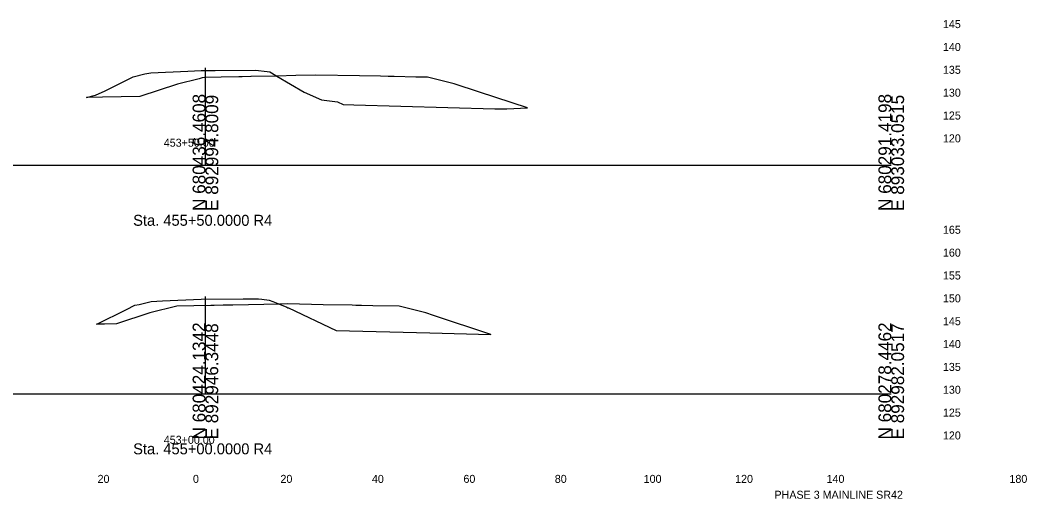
# Model space of a CAD drawing. Extents: x 21059 to 22955, y 6470 to 17494.
# Drawn here: x 21604.3 to 21824.5, y 7391.8 to 7496.6 of the extents above; entities that cross this region are included whole.
import ezdxf

# ---------------------------------------------------------------- set-up
doc = ezdxf.new("R2010")
doc.units = 0
for name, color, linetype in [('CONST_DCH', 7, 'Continuous'), ('Draft_XS_Grid', 7, 'Continuous'), ('Draft_XS_Text', 7, 'Continuous'), ('DTM CONTOURS_MAJOR', 7, 'Continuous'), ('SLOPE_STAKES_FILL', 7, 'Continuous'), ('X_PROFILES_1', 7, 'Continuous'), ('XS_SHEET_EW_TX_VOLUME', 7, 'Continuous')]:
    doc.layers.add(name, color=color, linetype=linetype)

msp = doc.modelspace()

# ---------------------------------------------------------------- linework, layer by layer
at = {"layer": 'DTM CONTOURS_MAJOR'}
for p, q in [((21644.84, 7464.84), (21644.84, 7486.16)), ((21494.84, 7464.84), (21644.84, 7464.84)), ((21644.84, 7464.84), (21794.84, 7464.84)), ((21644.84, 7414.84), (21644.84, 7436.1)), ((21494.84, 7414.84), (21644.84, 7414.84)), ((21644.84, 7414.84), (21794.84, 7414.84))]:
    msp.add_line(p, q, dxfattribs=at)
at = {"layer": 'XS_SHEET_EW_TX_VOLUME'}
for points in [[(21618.8, 7479.63), (21620.79, 7480.15), (21622.92, 7481.11), (21629.06, 7484.21), (21631.58, 7484.82), (21632.92, 7485.05), (21641.01, 7485.41), (21643.9, 7485.53), (21646.97, 7485.55), (21655.77, 7485.64), (21658.33, 7485.33), (21658.82, 7485.26), (21658.91, 7485.24), (21659.27, 7485.09), (21660.49, 7484.36), (21654.87, 7484.25), (21654.77, 7484.25), (21652.85, 7484.21), (21652.85, 7484.21), (21652.85, 7484.21), (21652.2, 7484.2), (21652.14, 7484.2), (21648.28, 7484.12), (21644.61, 7484.05), (21644.12, 7483.93), (21643.46, 7483.76), (21638.73, 7482.59), (21630.47, 7479.85), (21622.36, 7479.7)], [(21660.49, 7484.36), (21666.45, 7480.84), (21670.23, 7479.17), (21673.75, 7478.7), (21674.96, 7478.13), (21677.33, 7478.07), (21708.16, 7477.19), (21710.75, 7477.2), (21715.26, 7477.37), (21704.81, 7480.81), (21699.24, 7482.64), (21693.43, 7484.08), (21692.46, 7484.1), (21690.84, 7484.13), (21686.14, 7484.23), (21685.12, 7484.25), (21684.8, 7484.26), (21683.11, 7484.29), (21678.53, 7484.37), (21668.99, 7484.54), (21664.61, 7484.45)], [(21620.99, 7430.03), (21621.12, 7430.05), (21627.56, 7433.29), (21629.41, 7434.25), (21630.35, 7434.4), (21633, 7435.05), (21635.48, 7435.16), (21643.9, 7435.53), (21653.06, 7435.62), (21655.98, 7435.63), (21655.99, 7435.62), (21656.42, 7435.58), (21657.17, 7435.5), (21658.76, 7435.29), (21659.58, 7435.05), (21661.07, 7434.44), (21650.83, 7434.24), (21650.09, 7434.23), (21650.01, 7434.23), (21648.78, 7434.2), (21648.73, 7434.2), (21646.77, 7434.16), (21646.04, 7434.15), (21638.55, 7434), (21632.68, 7432.54), (21625.37, 7430.12), (21622.78, 7430.07)], [(21661.07, 7434.44), (21662.62, 7433.81), (21662.88, 7433.66), (21663, 7433.64), (21673.42, 7428.7), (21693.95, 7428.2), (21707.29, 7427.82), (21707.29, 7427.83), (21694.72, 7431.99), (21693.06, 7432.54), (21687.2, 7434), (21681.46, 7434.11), (21678.97, 7434.16), (21677.74, 7434.18), (21676.96, 7434.2), (21670.61, 7434.33), (21662.87, 7434.48)]]:
    msp.add_lwpolyline(points, close=True, dxfattribs=at)

# ---------------------------------------------------------------- texts
at = {"layer": 'CONST_DCH'}
for p in [(21630.43, 7479.79), (21630.43, 7479.79), (21715.22, 7477.31), (21715.22, 7477.31), (21625.33, 7430.06), (21625.33, 7430.06), (21707.25, 7427.77), (21707.25, 7427.77)]:
    msp.add_text('X', height=0.12, dxfattribs=at).set_placement(p)
at = {"layer": 'Draft_XS_Grid'}
for s, p in [('  145  ', (21804.84, 7494.84)), ('  140  ', (21804.84, 7489.84)), ('  135  ', (21804.84, 7484.84)), ('  130  ', (21804.84, 7479.84)), ('  125  ', (21804.84, 7474.84)), ('  120  ', (21804.84, 7469.84)), ('  165  ', (21804.84, 7449.84)), ('  160  ', (21804.84, 7444.84)), ('  155  ', (21804.84, 7439.84)), ('  150  ', (21804.84, 7434.84)), ('  145  ', (21804.84, 7429.84)), ('  140  ', (21804.84, 7424.84)), ('  135  ', (21804.84, 7419.84)), ('  130  ', (21804.84, 7414.84)), ('  125  ', (21804.84, 7409.84)), ('  120  ', (21804.84, 7404.84))]:
    msp.add_text(s, height=1.75, dxfattribs=at).set_placement(p)
at = {"layer": 'Draft_XS_Text'}
for s, p in [('  20  ', (21619.95, 7395.34)), ('  0  ', (21640.81, 7395.34)), ('  0  ', (21640.81, 7395.34)), ('  20  ', (21659.95, 7395.34)), ('  40  ', (21679.95, 7395.34)), ('  60  ', (21699.97, 7395.34)), ('  80  ', (21719.95, 7395.34)), ('  100  ', (21739.39, 7395.34)), ('  120  ', (21759.39, 7395.34)), ('  140  ', (21779.39, 7395.34)), ('  180  ', (21819.39, 7395.34)), ('PHASE 3 MAINLINE SR42', (21769.3, 7391.87))]:
    msp.add_text(s, height=1.75, dxfattribs=at).set_placement(p)
at = {"layer": 'DTM CONTOURS_MAJOR'}
for s, p in [('N 680436.4608', (21644.84, 7454.84)), ('E 892994.8009', (21647.64, 7454.84)), ('N 680291.4198', (21794.84, 7454.84)), ('E 893033.0515', (21797.64, 7454.84)), ('N 680424.1342', (21644.84, 7404.84)), ('E 892946.3448', (21647.64, 7404.84)), ('N 680278.4462', (21794.84, 7404.84)), ('E 892982.0517', (21797.64, 7404.84))]:
    msp.add_text(s, height=2.8, rotation=90, dxfattribs=at).set_placement(p)
at = {"layer": 'SLOPE_STAKES_FILL'}
for s, p in [('  453+50.00  ', (21634.43, 7468.89)), ('  453+00.00  ', (21634.43, 7403.89))]:
    msp.add_text(s, height=1.75, dxfattribs=at).set_placement(p)
at = {"layer": 'X_PROFILES_1'}
for s, p in [('Sta. 455+50.0000 R4', (21629.03, 7451.59)), ('Sta. 455+00.0000 R4', (21629.03, 7401.59))]:
    msp.add_text(s, height=2.4, dxfattribs=at).set_placement(p)

doc.saveas('drawing.dxf')
